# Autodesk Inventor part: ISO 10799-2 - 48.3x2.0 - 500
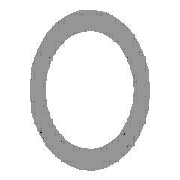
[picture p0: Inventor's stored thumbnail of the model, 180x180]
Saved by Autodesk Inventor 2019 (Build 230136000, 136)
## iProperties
Created: 2018-07
Part Number: ISO 10799-2 - 48.3x2.0 - 500
Material: Acier, doux
Description: Aciers de construction - Coupes creuses profilées formées à froid, soudées
Document SubType Name: Modeling
Standard: ISO
Designer: Fabian Perrée
Standard Revision: First edition 2011-09-15
Standards Organization: ISO
Language: fr-FR
Size Designation: 48.3x2.0
Categories: <MemberInstance><Categories><Category DisplayName="Profilés" InternalName="089c4875-fa83-4c05-b084-43b9cc11f5ed" Mnemonic="GRDR"><CategoryParameter DisplayName=
Stock Number: 48.3x2.0
Density: 7.85 g/cm^3
Appearance: Semi-poli
IsCustomPart: 1
_CCFamilyMember: 14
_CCFamilyDisplayName: ISO 10799-2 (Profils creux circulaires - Formés à froid) - Aciers de construction - Coupes creuses profilées formées à froid, soudées
_FrameMemberDoc: Frame Member File
_Version: 15.0.0
_GetPNFromCC: 1
Author: Fabian Perrée
G_L: 500,000 mm
G_W: 48,300 mm
G_H: 48,300 mm
+44A61AB8-31B7-4BA9-AADA-19D1380BA286+DETAILDECOUPE1: Grugeage
+8A7669E2-ED20-4943-939F-184320856275+DETAILDECOUPE2: Grugeage
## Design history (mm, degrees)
node "Plan de départ"
node "Plan de fin"
sketch "Esquisse"
  geometry: C1 r 22.15 at (0, 0); C2 r 24.15 at (0, 0); 2 further points
  constraints: 3 coincident, 2 centre point
  dimensions: "d0" = 48.3 diameter of C2 (= G_H); "d1" = 2 radial gap between concentric circles of C2 C1 (= G_T)
extrude "Corps" new body sketch "Esquisse" stored distance "d2" = 500 (= G_L); taper "d3" = 0 deg
node "Driven Length"
  sketch "Sketch3"
    geometry: L1 (0, 0)-(10, 0) reference
    constraints: 2 end point, 1 horizontal
  workplane "Work Plane3"
  sketch "Sketch4"
    geometry: L1 (-2, 0)-(12, 0) reference; L2 (-2, 500)-(12, 500) reference
    dimensions: "d7" = 500 distance between parallel lines of L1 L2 (derived)
body "Solid1"
feature "Sculpter1"
feature "Combiner1"
feature "Sculpter3"
feature "Combiner3"
body "Srf11"
body "Srf12"
node "Solide5"
body "Srf14"
body "Srf15"
node "Solide6"
feature "Surface1"
body "Srf10"
feature "Carreau délimité7" dims "d20" = 5, "d21" = 0
feature "Carreau délimité8" dims "d22" = 5, "d23" = 0
feature "Surface3"
body "Srf13"
feature "Carreau délimité9" dims "d24" = 5, "d25" = 0
feature "Carreau délimité10" dims "d26" = 5, "d27" = 0
other parameters: "G_H" = 48.3 [user parameter; used in 1 equation term], "G_T" = 2 [user parameter; used in 1 equation term], "G_L" = 500 (= d7) [user parameter; used in 1 equation term], "G_OFFSET_START" = 0 [user parameter; used in 1 equation term], "G_OFFSET_END" = 0 [user parameter; used in 1 equation term], "d4" = 0 (computed from G_OFFSET_START), "d5" = 500 (= G_OFFSET_END + B_L), "B_L" = 500 [user parameter; used in 1 equation term], "d6" = 90 deg, "MAS" = 0.228 [user parameter]
